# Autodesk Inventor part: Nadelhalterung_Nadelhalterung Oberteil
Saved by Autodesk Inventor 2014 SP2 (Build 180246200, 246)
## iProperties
Created: 2015-07
Part Number: Nadelhalterung_Nadelhalterung Oberteil
Material: Generisch
Document SubType Name: Modeling
Designer: e_krauts
Density: 1 g/cm^3
Appearance: Vorgabe
Author: e_krauts
Sending System: SolidWorks 2011
Last Author: e_boekem
Erstellt durch: XYZ
Werkstoff: AlCu4PbMg
Einheit: Stck.
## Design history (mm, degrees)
node "Nadelhalterung_Nadelhalterung Oberteil.ipt1"
node "Schnitt-Linear austragen1"
node "Basis1"
